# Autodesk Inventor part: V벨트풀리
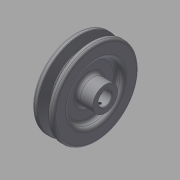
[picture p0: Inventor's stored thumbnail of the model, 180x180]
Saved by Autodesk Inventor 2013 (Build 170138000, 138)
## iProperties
Created: 2015-11
Part Number: V벨트풀리
Material: 강철, 탄소
Document SubType Name: Modeling
Designer: mduedu
Density: 7.87 g/cm^3
Mass: 425.959 g
Surface Area: 184.412 cm^2
Volume: 54.1244 cm^3
Author: mduedu
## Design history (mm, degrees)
sketch "스케치1"
  geometry: L1 (-9.5, 0)-(9.5, 0); L2 (0, 0)-(0, 37.7); L3 (-4.825, 37.7)-(-9.5, 37.7); L4 (-9.5, 37.7)-(-9.5, 0); L5 (0, 28.7)-(-2.074, 28.7); L6 (-2.074, 28.7)-(-4.825, 37.7); L7 (4.825, 37.7)-(9.5, 37.7); L8 (9.5, 37.7)-(9.5, 0); L9 (0, 28.7)-(2.074, 28.7); L10 (2.074, 28.7)-(4.825, 37.7); L11 (-9.5, 35)-(9.5, 35); 3 further points
  constraints: 22 end point, 7 point on line, 4 perpendicular, 3 symmetric about line, 1 coincident, 1 horizontal, 1 horizontal alignment, 1 midpoint, 1 vertical
  dimensions: "d0" = 19 distance of L1.start L1.end; "d2" = 75.4 diameter of L2.end L1 (derived); "d3" = 34 deg angle of L10 L6; "d4" = 6.3 distance between parallel lines of L11 L9; "d5" = 2.7 distance between parallel lines of L7 L11; "d6" = 8 distance of point (4, 35) point (-4, 35); "d7" = 70 diameter of L11 L1
revolve "회전1" sketch "스케치1" stored, may be unused: angle "d8" = 90 deg
sketch "스케치2"
  geometry: C1 r 24 at (0, 0); C2 r 11 at (0, 0); 1 further point
  constraints: 2 centre point, 2 coincident
  dimensions: "d9" = 48 diameter of C1; "d10" = 22 diameter of C2
extrude "돌출1" cut sketch "스케치2" distance "d11" = 6; taper "d12" = 0 deg
extrude "돌출3" join sketch "스케치2" distance "d37" = 8; taper "d38" = 0 deg
fillet "모깎기1" dims "d13" = 3
fillet "모깎기2" dims "d14" = 3
fillet "모깎기3" dims "d15" = 1, "d16" = 0.5, "d17" = 2
hole "구멍1" diameter "d20" = 12; stored, may be unused: countersink angle "d24" = 90 deg, drill point angle "d26" = 118 deg; dims "d21" = 6, "d22" = 4, "d23" = 2, "d25" = 8, "d58" = 10, "d59" = 10
sketch "스케치3"
  geometry: L1 (-2, 0)-(2, 0); L2 (2, 0)-(2, 7.8); L3 (2, 7.8)-(-2, 7.8); L4 (-2, 7.8)-(-2, 0); 2 further points
  constraints: 8 end point, 2 parallel, 1 coincident, 1 horizontal, 1 midpoint, 1 perpendicular
  dimensions: "d27" = 4 distance of L2.end L3.end; "d29" = 7.8 distance of L3.end L1.start
extrude "돌출2" cut sketch "스케치3" stored distance "d30" = 6; taper "d31" = 0 deg
node "작업 평면1"
sketch "스케치4"
  geometry: L1 (19, -27)-(19, 27) reference; 2 further points
  constraints: 1 horizontal alignment
  dimensions: "d52" = 22 distance from line of L1 point (-3, 0)
hole "구멍2" sketch "스케치4" at (-3, 0) diameter "d42" = 2.459; stored, may be unused: countersink angle "d46" = 90 deg, drill point angle "d48" = 118 deg; dims "d43" = 6, "d44" = 4, "d45" = 2, "d47" = 8
chamfer "모따기3" distance "d60" = 0.5; stored, may be unused: second distance "d61" = 2, angle "d62" = 45 deg
node "솔리드1"
mirror "대칭1"
